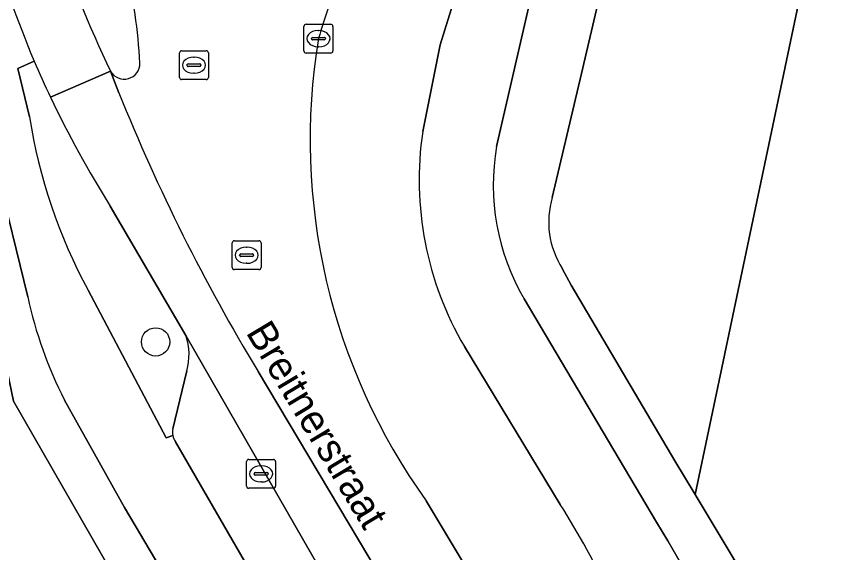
# Model space of a CAD drawing. Extents: x 161771 to 163125, y 382475 to 383179.
# Drawn here: x 162244.33 to 162273.01, y 383021.05 to 383039.61 of the extents above; entities that cross this region are included whole.
import ezdxf

# ---------------------------------------------------------------- set-up
doc = ezdxf.new("R2010")
doc.units = 0
for name, color, linetype in [('IMGEO_Berm_groen', 7, 'Continuous'), ('IMGEO_Boom', 7, 'Continuous'), ('IMGEO_Erf', 7, 'Continuous'), ('IMGEO_Fietspad_gesloten', 7, 'Continuous'), ('IMGEO_Groenvoorziening', 7, 'Continuous'), ('IMGEO_Kolk', 7, 'Continuous'), ('IMGEO_Openbare_ruimte_label', 7, 'Continuous'), ('IMGEO_Parkeervlak_open', 7, 'Continuous'), ('IMGEO_Rijbaan_lokaal_gesloten', 7, 'Continuous'), ('IMGEO_Rioolput', 7, 'Continuous'), ('IMGEO_Verkeerseiland_open', 7, 'Continuous'), ('IMGEO_Voetpad_open', 7, 'Continuous')]:
    doc.layers.add(name, color=color, linetype=linetype)

msp = doc.modelspace()

# ---------------------------------------------------------------- linework, layer by layer
at = {"layer": 'IMGEO_Berm_groen'}
for points in [[(162258.984, 383038.633), (162259.906, 383041.604), (162260.128, 383042.646)], [(162258.386, 383035.626), (162258.984, 383038.633)], [(162244.936, 383038.065), (162244.367, 383037.812), (162244.775, 383036.14)], [(162250.185, 383028.561), (162247.568, 383033.047)], [(162246.807, 383030.133), (162249.502, 383025.026), (162249.735, 383025.107)], [(162263.145, 383022.718), (162259.826, 383028.187)], [(162249.739, 383025.336), (162250.219, 383027.34)], [(162258.506, 383022.838), (162261.644, 383017.607), (162264.888, 383019.529)]]:
    msp.add_lwpolyline(points, dxfattribs=at)
for centre, radius, start, end in [((162282.918, 383030.592), 29.327, 159.0308, 163.6552), ((162275.958, 383035.343), 21.47, 170.6122, 215.6221), ((162277.106, 383051.903), 35.02, 203.2744, 205.5166), ((162279.377, 383052.93), 37.511, 205.4382, 212.0082), ((162263.297, 383039.058), 18.751, 188.954, 208.4245), ((162269.65, 383033.948), 11.389, 171.525, 210.386), ((162248.305, 383027.898), 1.993, 343.7547, 19.4354), ((162250.277, 383025.212), 0.552, 167.0283, 190.9703), ((162238.099, 383006.958), 29.592, 25.139, 32.18)]:
    msp.add_arc(centre, radius, start, end, dxfattribs=at)
at = {"layer": 'IMGEO_Boom'}
msp.add_circle((162249.141, 383028.345), 0.489, dxfattribs=at)
at = {"layer": 'IMGEO_Erf'}
for points in [[(162390.903, 383018.326), (162345.808, 383028.59), (162341.754, 383029.513), (162329.778, 383032.259), (162316.365, 383035.231), (162315.135, 383035.503), (162307.564, 383037.18), (162307.693, 383037.758), (162286.531, 383042.481), (162272.573, 383045.648), (162271.942, 383042.707), (162267.815, 383023.058), (162269.166, 383020.806), (162271.44, 383017.015), (162271.642, 383016.678), (162282.561, 382998.663), (162282.694, 382998.745), (162285.645, 382993.994)], [(162265.135, 382993.636), (162262.556, 382997.957), (162262.365, 382998.277), (162261.74, 382999.324), (162260.234, 382998.399), (162259.692, 382998.126), (162257.482, 382998.695), (162259.402, 382999.848), (162259.315, 383000), (162244.219, 383026.291), (162241.992, 383037.016), (162236.909, 383038.191), (162235.21, 383038.577), (162234.544, 383035.577), (162234.18, 383033.937), (162237.732, 383028.397), (162238.726, 383029.045), (162238.997, 383028.624), (162237.993, 383027.987), (162239.092, 383026.259), (162236.485, 383024.601), (162252.111, 383000), (162254.878, 382995.644)]]:
    msp.add_lwpolyline(points, dxfattribs=at)
at = {"layer": 'IMGEO_Fietspad_gesloten'}
for points in [[(162261.301, 383047.66), (162260.99, 383046.37), (162260.966, 383046.265), (162260.128, 383042.646), (162259.906, 383041.604), (162258.984, 383038.633), (162258.386, 383035.626)], [(162260.939, 383035.114), (162263.009, 383044.129)], [(162245.502, 383036.817), (162247.584, 383037.714)], [(162267.436, 383014.181), (162271.227, 383004.056), (162273.743, 383004.937), (162272.387, 383008.736), (162270.119, 383014.6), (162269.582, 383015.918), (162268.749, 383017.818), (162268.188, 383019.062), (162267.734, 383019.951), (162266.865, 383021.456), (162266.476, 383022.107), (162261.893, 383029.84)], [(162259.826, 383028.187), (162263.145, 383022.718)]]:
    msp.add_lwpolyline(points, dxfattribs=at)
for centre, radius, start, end in [((162284.642, 383055.525), 41.115, 198.342, 205.6698), ((162333.223, 383073.685), 95.202, 199.19524, 201.97208), ((162277.106, 383051.903), 35.02, 203.2744, 205.5166), ((162269.65, 383033.948), 11.389, 171.525, 210.386), ((162268.598, 383033.776), 7.775, 170.0924, 210.4141), ((162238.099, 383006.958), 29.592, 25.139, 32.18)]:
    msp.add_arc(centre, radius, start, end, dxfattribs=at)
at = {"layer": 'IMGEO_Groenvoorziening'}
for points in [[(162271.942, 383042.707), (162272.573, 383045.648), (162270.371, 383046.129), (162268.035, 383046.649), (162266.078, 383047.062), (162263.883, 383037.637), (162262.868, 383033.348)], [(162263.215, 383030.886), (162263.52, 383030.304), (162267.114, 383024.227), (162267.815, 383023.058), (162271.942, 383042.707)], [(162242.642, 383038.727), (162241.63, 383038.949), (162241.992, 383037.016), (162244.219, 383026.291), (162259.315, 383000), (162259.402, 382999.848), (162260.234, 382998.399), (162261.74, 382999.324), (162258.681, 383004.654), (162256.308, 383008.673), (162248.068, 383022.61), (162245.985, 383026.331)], [(162244.714, 383029.905), (162243.636, 383034.288), (162242.642, 383038.727)]]:
    msp.add_lwpolyline(points, dxfattribs=at)
for centre, radius, start, end in [((162265.707, 383032.493), 2.965, 163.237, 212.8081), ((162259.339, 383033.093), 14.969, 192.2973, 206.8559)]:
    msp.add_arc(centre, radius, start, end, dxfattribs=at)
at = {"layer": 'IMGEO_Kolk'}
for p, q in [((162254.35, 383039.345), (162255.202, 383039.345)), ((162254.275, 383038.419), (162254.275, 383039.271)), ((162254.763, 383039.125), (162254.788, 383039.125)), ((162255.276, 383039.271), (162255.276, 383038.419)), ((162254.534, 383038.839), (162254.534, 383038.851)), ((162254.972, 383038.802), (162254.574, 383038.802)), ((162254.577, 383038.888), (162254.975, 383038.888)), ((162255.018, 383038.851), (162255.018, 383038.839)), ((162254.786, 383038.565), (162254.761, 383038.565)), ((162255.202, 383038.345), (162254.35, 383038.345)), ((162252.291, 383023.349), (162252.291, 383024.201)), ((162252.366, 383024.275), (162253.218, 383024.275)), ((162253.292, 383024.201), (162253.292, 383023.349)), ((162252.779, 383024.055), (162252.804, 383024.055)), ((162252.55, 383023.769), (162252.55, 383023.781)), ((162252.988, 383023.732), (162252.59, 383023.732)), ((162252.593, 383023.818), (162252.991, 383023.818)), ((162253.034, 383023.781), (162253.034, 383023.769)), ((162253.218, 383023.275), (162252.366, 383023.275)), ((162252.802, 383023.495), (162252.777, 383023.495))]:
    msp.add_line(p, q, dxfattribs=at)
for points in [[(162254.35, 383039.345), (162255.202, 383039.345)], [(162254.275, 383038.419), (162254.275, 383039.271)], [(162255.276, 383039.271), (162255.276, 383038.419)], [(162255.202, 383038.345), (162254.35, 383038.345)], [(162252.291, 383023.349), (162252.291, 383024.201)], [(162252.366, 383024.275), (162253.218, 383024.275)], [(162253.292, 383024.201), (162253.292, 383023.349)], [(162253.218, 383023.275), (162252.366, 383023.275)]]:
    msp.add_lwpolyline(points, dxfattribs=at)
for centre, radius, start, end in [((162254.352, 383039.269), 0.0765, 91.552, 178.448), ((162254.352, 383039.269), 0.0765, 91.552, 178.448), ((162255.2, 383039.269), 0.0765, 1.552, 88.448), ((162255.2, 383039.269), 0.0765, 1.552, 88.448), ((162254.574, 383038.848), 0.0403, 85.8775, 175.7526), ((162254.571, 383038.838), 0.0366, 178.938, 274.7102), ((162254.975, 383038.845), 0.043, 264.8664, 352.4533), ((162254.979, 383038.85), 0.0386, 1.7309, 96.639), ((162254.352, 383038.421), 0.0765, 181.552, 268.448), ((162254.352, 383038.421), 0.0765, 181.552, 268.448), ((162255.2, 383038.421), 0.0765, 271.552, 358.448), ((162255.2, 383038.421), 0.0765, 271.552, 358.448), ((162252.368, 383024.199), 0.0765, 91.552, 178.448), ((162252.368, 383024.199), 0.0765, 91.552, 178.448), ((162253.216, 383024.199), 0.0765, 1.552, 88.448), ((162253.216, 383024.199), 0.0765, 1.552, 88.448), ((162252.59, 383023.778), 0.0403, 85.8775, 175.7526), ((162252.587, 383023.768), 0.0366, 178.938, 274.7102), ((162252.991, 383023.775), 0.043, 264.8664, 352.4533), ((162252.995, 383023.78), 0.0386, 1.7309, 96.639), ((162252.368, 383023.351), 0.0765, 181.552, 268.448), ((162252.368, 383023.351), 0.0765, 181.552, 268.448), ((162253.216, 383023.351), 0.0765, 271.552, 358.448), ((162253.216, 383023.351), 0.0765, 271.552, 358.448)]:
    msp.add_arc(centre, radius, start, end, dxfattribs=at)
for centre, major_axis, ratio, start_param, end_param in [((162254.762, 383038.845), (-0.387, 0.002), 0.722429, 4.712389, 7.853982), ((162254.787, 383038.845), (-0.39, 0.002), 0.717154, 1.570796, 4.712389), ((162252.778, 383023.775), (-0.387, 0.002), 0.722429, 4.712389, 7.853982), ((162252.803, 383023.775), (-0.39, 0.002), 0.717154, 1.570796, 4.712389)]:
    msp.add_ellipse(centre, major_axis=major_axis, ratio=ratio, start_param=start_param, end_param=end_param, dxfattribs=at)
at = {"layer": 'IMGEO_Parkeervlak_open'}
for points in [[(162262.588, 383003.433), (162266.739, 383000.473), (162255.729, 383018.904), (162250.185, 383028.561)], [(162250.219, 383027.34), (162249.739, 383025.336)], [(162249.832, 383024.889), (162253.882, 383017.878), (162262.393, 383003.656)]]:
    msp.add_lwpolyline(points, dxfattribs=at)
for centre, radius, start, end in [((162248.305, 383027.898), 1.993, 343.7547, 19.4354), ((162250.277, 383025.212), 0.552, 167.0283, 190.9703), ((162250.261, 383025.21), 0.536, 191.1192, 216.8546)]:
    msp.add_arc(centre, radius, start, end, dxfattribs=at)
at = {"layer": 'IMGEO_Rijbaan_lokaal_gesloten'}
for points in [[(162247.871, 383036.965), (162247.584, 383037.714), (162245.502, 383036.817)], [(162247.584, 383037.714), (162247.871, 383036.965)], [(162247.568, 383033.047), (162250.185, 383028.561), (162255.729, 383018.904), (162266.739, 383000.473), (162269.326, 382996.118)], [(162252.687, 383027.32), (162258.27, 383017.942), (162277.114, 382986.385), (162314.204, 382923.986), (162330.304, 382896.843), (162338.934, 382882.25), (162339.793, 382880.803)], [(162277.114, 382986.385), (162258.27, 383017.942), (162252.687, 383027.32)], [(162270.123, 383003.466), (162264.827, 383012.253), (162264.658, 383012.57), (162261.644, 383017.607), (162258.506, 383022.838)]]:
    msp.add_lwpolyline(points, dxfattribs=at)
for centre, radius, start, end in [((162229.462, 383036.999), 19.16, 2.9865, 13.1447), ((162282.918, 383030.592), 29.327, 159.0308, 163.6552), ((162275.958, 383035.343), 21.47, 170.6122, 215.6221), ((162248.053, 383037.986), 0.543, 210.1336, 1.1131), ((162279.377, 383052.93), 37.511, 205.4382, 212.0082), ((162310.07, 383061.998), 67.047, 201.92289, 211.14541), ((162310.07, 383061.998), 67.047, 201.92289, 211.14541)]:
    msp.add_arc(centre, radius, start, end, dxfattribs=at)
at = {"layer": 'IMGEO_Rioolput'}
for p, q in [((162249.967, 383037.502), (162249.967, 383038.354)), ((162250.042, 383038.428), (162250.894, 383038.428)), ((162250.455, 383038.208), (162250.48, 383038.208)), ((162250.968, 383038.354), (162250.968, 383037.502)), ((162250.226, 383037.922), (162250.226, 383037.934)), ((162250.269, 383037.971), (162250.667, 383037.971)), ((162250.71, 383037.934), (162250.71, 383037.922)), ((162250.664, 383037.885), (162250.266, 383037.885)), ((162250.478, 383037.648), (162250.453, 383037.648)), ((162250.894, 383037.428), (162250.042, 383037.428)), ((162251.79, 383030.921), (162251.79, 383031.773)), ((162251.865, 383031.847), (162252.717, 383031.847)), ((162252.278, 383031.627), (162252.303, 383031.627)), ((162252.791, 383031.773), (162252.791, 383030.921)), ((162252.049, 383031.341), (162252.049, 383031.353)), ((162252.487, 383031.304), (162252.089, 383031.304)), ((162252.092, 383031.39), (162252.49, 383031.39)), ((162252.533, 383031.353), (162252.533, 383031.341)), ((162252.301, 383031.067), (162252.276, 383031.067)), ((162252.717, 383030.847), (162251.865, 383030.847))]:
    msp.add_line(p, q, dxfattribs=at)
for points in [[(162249.967, 383037.502), (162249.967, 383038.354)], [(162250.042, 383038.428), (162250.894, 383038.428)], [(162250.968, 383038.354), (162250.968, 383037.502)], [(162250.894, 383037.428), (162250.042, 383037.428)], [(162251.79, 383030.921), (162251.79, 383031.773)], [(162251.865, 383031.847), (162252.717, 383031.847)], [(162252.791, 383031.773), (162252.791, 383030.921)], [(162252.717, 383030.847), (162251.865, 383030.847)]]:
    msp.add_lwpolyline(points, dxfattribs=at)
for centre, radius, start, end in [((162250.044, 383038.352), 0.0765, 91.552, 178.448), ((162250.044, 383038.352), 0.0765, 91.552, 178.448), ((162250.892, 383038.352), 0.0765, 1.552, 88.448), ((162250.892, 383038.352), 0.0765, 1.552, 88.448), ((162250.266, 383037.931), 0.0403, 85.8775, 175.7526), ((162250.263, 383037.921), 0.0366, 178.938, 274.7102), ((162250.667, 383037.928), 0.043, 264.8664, 352.4533), ((162250.671, 383037.933), 0.0386, 1.7309, 96.639), ((162250.044, 383037.504), 0.0765, 181.552, 268.448), ((162250.044, 383037.504), 0.0765, 181.552, 268.448), ((162250.892, 383037.504), 0.0765, 271.552, 358.448), ((162250.892, 383037.504), 0.0765, 271.552, 358.448), ((162251.867, 383031.771), 0.0765, 91.552, 178.448), ((162251.867, 383031.771), 0.0765, 91.552, 178.448), ((162252.715, 383031.771), 0.0765, 1.552, 88.448), ((162252.715, 383031.771), 0.0765, 1.552, 88.448), ((162252.089, 383031.35), 0.0403, 85.8775, 175.7526), ((162252.086, 383031.34), 0.0366, 178.938, 274.7102), ((162252.49, 383031.347), 0.043, 264.8664, 352.4533), ((162252.494, 383031.352), 0.0386, 1.7309, 96.639), ((162251.867, 383030.923), 0.0765, 181.552, 268.448), ((162251.867, 383030.923), 0.0765, 181.552, 268.448), ((162252.715, 383030.923), 0.0765, 271.552, 358.448), ((162252.715, 383030.923), 0.0765, 271.552, 358.448)]:
    msp.add_arc(centre, radius, start, end, dxfattribs=at)
for centre, major_axis, ratio, start_param, end_param in [((162250.454, 383037.928), (-0.387, 0.002), 0.722429, 4.712389, 7.853982), ((162250.479, 383037.928), (-0.39, 0.002), 0.717154, 1.570796, 4.712389), ((162252.277, 383031.347), (-0.387, 0.002), 0.722429, 4.712389, 7.853982), ((162252.302, 383031.347), (-0.39, 0.002), 0.717154, 1.570796, 4.712389)]:
    msp.add_ellipse(centre, major_axis=major_axis, ratio=ratio, start_param=start_param, end_param=end_param, dxfattribs=at)
at = {"layer": 'IMGEO_Verkeerseiland_open'}
for centre, radius, start, end in [((162284.642, 383055.525), 41.115, 198.342, 205.6698), ((162229.462, 383036.999), 19.16, 2.9865, 13.1447), ((162248.053, 383037.986), 0.543, 210.1336, 1.1131)]:
    msp.add_arc(centre, radius, start, end, dxfattribs=at)
at = {"layer": 'IMGEO_Voetpad_open'}
for points in [[(162264.059, 383048.53), (162263.009, 383044.129), (162260.939, 383035.114)], [(162263.883, 383037.637), (162266.078, 383047.062), (162266.199, 383047.671), (162266.41, 383048.624)], [(162243.314, 383042.384), (162243.022, 383043.077), (162242.054, 383043.244), (162242.642, 383038.727), (162243.636, 383034.288), (162244.714, 383029.905)], [(162244.775, 383036.14), (162244.367, 383037.812), (162244.936, 383038.065)], [(162262.868, 383033.348), (162263.883, 383037.637)], [(162261.893, 383029.84), (162266.476, 383022.107), (162266.865, 383021.456), (162267.734, 383019.951), (162269.166, 383020.806), (162267.815, 383023.058), (162267.114, 383024.227), (162263.52, 383030.304), (162263.215, 383030.886)], [(162249.735, 383025.107), (162249.502, 383025.026), (162246.807, 383030.133)], [(162245.985, 383026.331), (162248.068, 383022.61), (162256.308, 383008.673), (162258.681, 383004.654), (162261.74, 382999.324), (162262.365, 382998.277), (162262.556, 382997.957), (162264.761, 382999.277), (162262.33, 383003.335), (162262.471, 383003.535)], [(162262.393, 383003.656), (162253.882, 383017.878), (162249.832, 383024.889)]]:
    msp.add_lwpolyline(points, dxfattribs=at)
for centre, radius, start, end in [((162333.223, 383073.685), 95.202, 199.19524, 201.97208), ((162263.297, 383039.058), 18.751, 188.954, 208.4245), ((162268.598, 383033.776), 7.775, 170.0924, 210.4141), ((162265.707, 383032.493), 2.965, 163.237, 212.8081), ((162259.339, 383033.093), 14.969, 192.2973, 206.8559), ((162250.261, 383025.21), 0.536, 191.1192, 216.8546)]:
    msp.add_arc(centre, radius, start, end, dxfattribs=at)

# ---------------------------------------------------------------- texts
at = {"layer": 'IMGEO_Openbare_ruimte_label'}
msp.add_text('Breitnerstraat', height=1, rotation=300.9245, dxfattribs=at).set_placement((162252.246, 383028.672))

doc.saveas('drawing.dxf')
